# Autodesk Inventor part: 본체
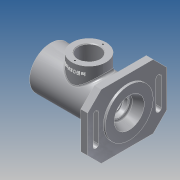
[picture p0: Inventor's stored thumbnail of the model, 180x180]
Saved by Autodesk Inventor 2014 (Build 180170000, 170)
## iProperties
Created: 2017-10
Part Number: 본체
Material: 알루미늄 6061
Document SubType Name: Modeling
Designer: kb542-14
Density: 2.71 g/cm^3
Appearance: 알루미늄 - 평지
Mass: 738.128 g
Surface Area: 650.976 cm^2
Volume: 272.372 cm^3
Author: kb542-14
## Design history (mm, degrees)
sketch "스케치1"
  geometry: L1 (-57.5, 0)-(57.5, 0); L2 (-57.5, 21)-(-48.5, 21); L3 (-48.5, 21)-(-48.5, 24); L4 (-48.5, 24)-(-45.5, 24); L5 (-45.5, 24)-(-45.5, 20); L6 (-45.5, 20)-(-36.5, 20); L7 (-36.5, 20)-(-36.5, 17.5); L8 (-36.5, 17.5)-(-33.25, 17.5); L9 (-33.25, 17.5)-(-33.25, 18.5); L10 (-33.25, 18.5)-(-31.5, 18.5); L11 (-31.5, 18.5)-(-31.5, 17.5); L12 (-31.5, 17.5)-(-20.5, 17.5); L13 (-20.5, 17.5)-(-20.5, 26); L14 (-20.5, 26)-(17.5, 26); L15 (17.5, 26)-(17.5, 17.5); L16 (17.5, 17.5)-(28.2, 17.5); L17 (28.5, 17.2)-(28.5, 16.5); L18 (28.5, 16.5)-(30.5, 16.5); L19 (33.5, 13.5)-(33.5, 10); L20 (33.5, 10)-(36.2, 10); L21 (36.2, 10)-(36.2, 12.2); L22 (36.5, 12.5)-(42.8, 12.5); L23 (57.5, 22)-(57.5, 35); L24 (57.5, 35)-(44.5, 35); L25 (44.5, 31)-(-57.5, 31); L26 (-57.5, 31)-(-57.5, 21); L27 (44.5, 31)-(44.5, 35); L28 (42.8, 12.5)-(43.5, 12.904); L29 (43.5, 12.904)-(43.5, 14.022); L30 (45.318, 16.779)-(57.5, 22); A1 r 3 centre (46.5, 14.022) between (45.318, 16.779) and (43.5, 14.022); A2 r 3 centre (30.5, 13.5) between (33.5, 13.5) and (30.5, 16.5); A3 r 0.3 centre (36.5, 12.2) between (36.5, 12.5) and (36.2, 12.2); A4 r 0.3 centre (28.2, 17.2) between (28.5, 17.2) and (28.2, 17.5); 6 further points
  constraints: 60 end point, 26 parallel, 8 point on circle, 8 point on line, 8 tangent, 4 centre point, 2 equal radius, 2 vertical alignment, 1 coincident, 1 horizontal, 1 midpoint, 1 perpendicular
  dimensions: "d0" = 62 diameter of L25 L1; "d1" = 48 diameter of L4 L1; "d2" = 42 diameter of L2 L1; "d4" = 40 diameter of L6 L1; "d5" = 35 diameter of L8 L1; "d6" = 37 diameter of L10 L1; "d7" = 35 diameter of L12 L1; "d8" = 52 diameter of L14 L1; "d9" = 35 diameter of L16 L1; "d10" = 33 diameter of L18 L1; "d11" = 20 diameter of L20 L1; "d13" = 115 distance between parallel lines of L23 L26; "d14" = 3 distance between parallel lines of L5 L3; "d15" = 12 distance between parallel lines of L5 L26; "d16" = 38 distance between parallel lines of L15 L13; "d17" = 21 distance between parallel lines of L26 L7; "d18" = 1.75 distance between parallel lines of L11 L9; "d19" = 26 distance between parallel lines of L26 L11; "d20" = 11 distance between parallel lines of L13 L11; "d23" = 70 diameter of L24 L1; "d24" = 13 distance between parallel lines of L27 L23; "d26" = 2.7 distance between parallel lines of L21 L19; "d27" = 11 distance between parallel lines of L17 L15; "d28" = 44 diameter of L23.start L1; "d31" = 7.3 distance from line of point (43.5, 16) L21; "d32" = 32 diameter of point (43.5, 16) L1; "d35" = 25 diameter of L22 L1; "d36" = 0.7 distance from line of L22.end L29; "d37" = 30 deg angle of L28 L22; "d82" = 3 radius of A1; "d83" = 0.3 radius of A3; "d87" = 14 distance from line of L28.end L23
revolve "회전1" sketch "스케치1" stored, may be unused: angle "d38" = 90 deg
node "작업 평면1"
sketch "스케치2"
  geometry: L1 (-58, -47)-(58, -47); L2 (58, -47)-(58, 47); L3 (58, 47)-(-58, 47); L4 (-58, 47)-(-58, -47); L5 (-58, -47)-(58, 47); L6 (58, -47)-(-58, 47); C1 r 35 at (0, 0) reference; C2 r 22 at (0, 0) reference; 3 further points
  constraints: 12 end point, 3 midpoint, 2 parallel, 1 coincident, 1 horizontal, 1 perpendicular
  dimensions: "d40" = 94 distance between parallel lines of L3 L1; "d41" = 116 distance between parallel lines of L2 L4
extrude "돌출1" join sketch "스케치2" distance "d42" = 10; taper "d43" = 0 deg
chamfer "모따기1" distance "d44" = 20; stored, may be unused: second distance "d45" = 2, angle "d46" = 45 deg
sketch "스케치3"
  geometry: L1 (94, 0)-(94, 76) reference; L2 (27, 84)-(67, 84); L3 (27, 88)-(67, 88); L4 (67, 80)-(27, 80); C1 r 31 at (47, 38) reference; A1 r 4 centre (27, 84) between (27, 88) and (27, 80); A2 r 4 centre (67, 84) between (67, 80) and (67, 88); 1 further point
  constraints: 8 end point, 4 point on circle, 4 tangent, 2 centre point, 1 midpoint, 1 parallel, 1 perpendicular, 1 vertical alignment
  dimensions: "d47" = 40 distance of L2.start L2.end; "d48" = 4 radius of A1; "d49" = 46 distance of point (47, 84) C1.centre
extrude "돌출2" cut sketch "스케치3" stored distance "d50" = 10; taper "d51" = 0 deg
feature "스레드1" dims "d52" = 9, "d53" = 0
node "작업 평면2"
sketch "스케치4"
  geometry: L1 (-57.5, -31)-(-57.5, 31) reference; C1 r 25 at (-1.5, 0); 2 further points
  constraints: 1 centre point, 1 horizontal alignment, 1 midpoint
  dimensions: "d55" = 50 diameter of C1; "d56" = 56 distance from line of C1.centre L1
extrude "돌출3" join sketch "스케치4" stored distance "d57" = 10; taper "d58" = 0 deg
sketch "스케치5"
  geometry: C1 r 25 at (0, 0) reference; C2 r 16 at (0, 0); 1 further point
  constraints: 1 centre point, 1 coincident
  dimensions: "d59" = 32 diameter of C2
extrude "돌출4" cut sketch "스케치5" stored distance "d60" = 10; taper "d61" = 0 deg
chamfer "모따기2" distance "d62" = 1; stored, may be unused: second distance "d63" = 2, angle "d64" = 45 deg
sketch "스케치6" dims "d65" = 41
  geometry: C1 r 25 at (0, 0) reference; C2 r 17 at (0, 0) reference; 3 further points
  constraints: 2 vertical alignment, 1 coincident, 2 other
hole "구멍1" sketch "스케치6" at (0, 20.5) diameter "d66" = 2.459; stored, may be unused: countersink angle "d70" = 90 deg, drill point angle "d72" = 118 deg; dims "d67" = 6, "d68" = 4, "d69" = 2, "d71" = 8
fillet "모깎기1" dims "d76" = 3
node "작업 평면3"
sketch "스케치7"
  geometry: L1 (-25, 0)-(25, 0) reference; L2 (-56, -78)-(-56, -16) reference; 2 further points
  constraints: 1 other
  dimensions: "d77" = 10 distance from line of point (0, -10) L1; "d78" = 56 distance from line of point (0, -10) L2
feature "엠보싱1" sketch "스케치7" dims "d2" = 42, "d79" = 0.5, "d80" = 0
fillet "모깎기2" dims "d81" = 3
chamfer "모따기3" distance "d84" = 1; stored, may be unused: second distance "d85" = 2, angle "d86" = 45 deg
node "솔리드1"
mirror "대칭1"
pattern_circular "원형 패턴1" dims angle "d74" = 360 deg
node "투영된 루프1"
other parameters: "d39" = -3, "d54" = 47
